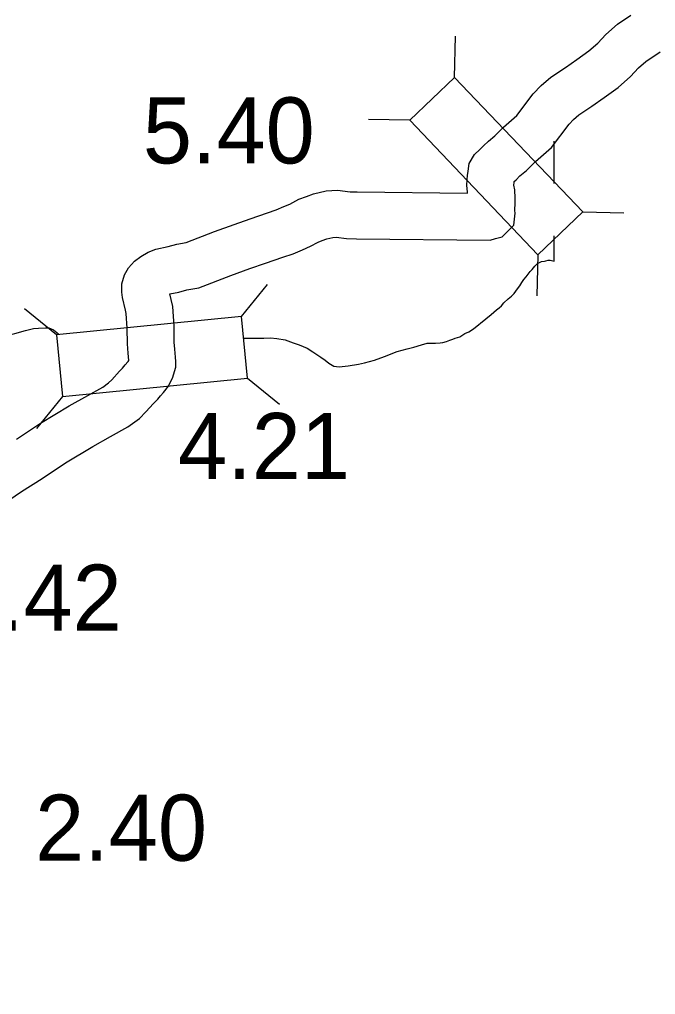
# Model space of a CAD drawing. Extents: x 0 to 3171, y 0 to 2059.
# Drawn here: x 276 to 357.4, y 1415.2 to 1539.9 of the extents above; entities that cross this region are included whole.
import ezdxf

# ---------------------------------------------------------------- set-up
doc = ezdxf.new("R2010")
doc.units = 0
for name, color, linetype in [('Default', 7, 'Continuous'), ('Level 10', 7, 'Continuous'), ('Level 20', 7, 'Continuous'), ('Level 58', 7, 'Continuous'), ('Level 8', 7, 'Continuous')]:
    doc.layers.add(name, color=color, linetype=linetype)

msp = doc.modelspace()

# ---------------------------------------------------------------- linework, layer by layer
at = {"layer": 'Default'}
msp.add_circle((410.95, 1647.45), 386.47, dxfattribs=at)
msp.add_circle((410.95, 1647.45), 386.47, dxfattribs=at)
at = {"layer": 'Level 10'}
for points in [[(275.61, 1486.19), (278.67, 1488.24), (282.36, 1490.48), (284.75, 1491.8), (286.64, 1492.85), (287.4, 1493.4), (287.79, 1493.82), (288.79, 1494.89), (289.18, 1495.3), (289.51, 1495.71), (289.87, 1496.09), (289.92, 1496.15), (289.98, 1496.28), (289.89, 1497.21), (289.8, 1498.39), (289.79, 1500.42), (289.66, 1502.27), (289.55, 1502.72), (289.18, 1504.35), (289.1, 1505.03), (289.1, 1506.1), (289.42, 1507.24), (289.96, 1508.14), (290.72, 1508.97), (291.54, 1509.58), (292.46, 1510.13), (293.45, 1510.53), (295.01, 1510.87), (296.14, 1511.16), (297.31, 1511.37), (300.95, 1512.77), (303.47, 1513.68), (305.51, 1514.38), (307.73, 1515.15), (308.85, 1515.54), (309.81, 1515.95), (310.58, 1516.29), (311.72, 1516.91), (312.71, 1517.27), (313.62, 1517.59), (315.21, 1517.96), (316.7, 1518.05), (318.28, 1517.85), (319.18, 1517.83), (333.33, 1517.69), (333.3, 1517.85), (333.22, 1518.65), (333.28, 1519.44), (333.31, 1519.95), (333.39, 1520.5), (333.54, 1521.49), (334.22, 1522.61), (334.88, 1523.28), (335.36, 1523.73), (335.99, 1524.33), (336.8, 1525.02), (337.92, 1526.12), (339.63, 1527.63), (341.71, 1530.4), (342.72, 1531.46), (343.96, 1532.52), (345.84, 1533.75), (347.31, 1534.79), (348.85, 1535.89), (349.97, 1536.88), (350.99, 1537.99), (352.48, 1539.3), (354.21, 1540.45)], [(275.61, 1486.19), (278.67, 1488.24), (282.36, 1490.48), (284.75, 1491.8), (286.64, 1492.85), (287.4, 1493.4), (287.79, 1493.82), (288.79, 1494.89), (289.18, 1495.3), (289.51, 1495.71), (289.87, 1496.09), (289.92, 1496.15), (289.98, 1496.28), (289.89, 1497.21), (289.8, 1498.39), (289.79, 1500.42), (289.66, 1502.27), (289.55, 1502.72), (289.18, 1504.35), (289.1, 1505.03), (289.1, 1506.1), (289.42, 1507.24), (289.96, 1508.14), (290.72, 1508.97), (291.54, 1509.58), (292.46, 1510.13), (293.45, 1510.53), (295.01, 1510.87), (296.14, 1511.16), (297.31, 1511.37), (300.95, 1512.77), (303.47, 1513.68), (305.51, 1514.38), (307.73, 1515.15), (308.85, 1515.54), (309.81, 1515.95), (310.58, 1516.29), (311.72, 1516.91), (312.71, 1517.27), (313.62, 1517.59), (315.21, 1517.96), (316.7, 1518.05), (318.28, 1517.85), (319.18, 1517.83), (333.33, 1517.69), (333.3, 1517.85), (333.22, 1518.65), (333.28, 1519.44), (333.31, 1519.95), (333.39, 1520.5), (333.54, 1521.49), (334.22, 1522.61), (334.88, 1523.28), (335.36, 1523.73), (335.99, 1524.33), (336.8, 1525.02), (337.92, 1526.12), (339.63, 1527.63), (341.71, 1530.4), (342.72, 1531.46), (343.96, 1532.52), (345.84, 1533.75), (347.31, 1534.79), (348.85, 1535.89), (349.97, 1536.88), (350.99, 1537.99), (352.48, 1539.3), (354.21, 1540.45)], [(273.08, 1477.38), (276.26, 1479.51), (278.88, 1481.16), (281.9, 1483.18), (285.37, 1485.29), (287.66, 1486.56), (289.85, 1487.78), (291.37, 1488.86), (292.18, 1489.72), (293.15, 1490.77), (293.68, 1491.32), (294.02, 1491.75), (294.43, 1492.17), (295.06, 1492.99), (295.62, 1494.16), (295.72, 1494.46), (295.99, 1495.43), (295.99, 1496.15), (295.97, 1496.71), (295.87, 1497.73), (295.8, 1498.63), (295.78, 1500.65), (295.61, 1503.16), (295.4, 1504.07), (295.23, 1504.78), (296.39, 1505.03), (297.41, 1505.3), (298.92, 1505.56), (303.04, 1507.14), (305.47, 1508.02), (307.47, 1508.71), (309.69, 1509.48), (311, 1509.93), (312.2, 1510.44), (313.23, 1510.9), (314.21, 1511.43), (314.73, 1511.62), (315.3, 1511.82), (316.08, 1512), (316.5, 1512.03), (317.84, 1511.86), (319.09, 1511.83), (336.22, 1511.66), (336.89, 1511.87), (337.75, 1512.11), (339.23, 1513.58), (339.4, 1515.12), (339.37, 1515.48), (339.37, 1515.65), (339.39, 1516.29), (339.39, 1517.03), (339.36, 1518.11), (339.25, 1518.72), (339.27, 1519.06), (339.28, 1519.17), (339.52, 1519.4), (340.01, 1519.88), (340.85, 1520.59), (342, 1521.72), (344.06, 1523.53), (346.3, 1526.51), (346.85, 1527.09), (347.57, 1527.71), (349.22, 1528.79), (350.79, 1529.9), (352.6, 1531.19), (354.17, 1532.59), (355.19, 1533.69), (356.14, 1534.53), (357.97, 1535.74)], [(273.08, 1477.38), (276.26, 1479.51), (278.88, 1481.16), (281.9, 1483.18), (285.37, 1485.29), (287.66, 1486.56), (289.85, 1487.78), (291.37, 1488.86), (292.18, 1489.72), (293.15, 1490.77), (293.68, 1491.32), (294.02, 1491.75), (294.43, 1492.17), (295.06, 1492.99), (295.62, 1494.16), (295.72, 1494.46), (295.99, 1495.43), (295.99, 1496.15), (295.97, 1496.71), (295.87, 1497.73), (295.8, 1498.63), (295.78, 1500.65), (295.61, 1503.16), (295.4, 1504.07), (295.23, 1504.78), (296.39, 1505.03), (297.41, 1505.3), (298.92, 1505.56), (303.04, 1507.14), (305.47, 1508.02), (307.47, 1508.71), (309.69, 1509.48), (311, 1509.93), (312.2, 1510.44), (313.23, 1510.9), (314.21, 1511.43), (314.73, 1511.62), (315.3, 1511.82), (316.08, 1512), (316.5, 1512.03), (317.84, 1511.86), (319.09, 1511.83), (336.22, 1511.66), (336.89, 1511.87), (337.75, 1512.11), (339.23, 1513.58), (339.4, 1515.12), (339.37, 1515.48), (339.37, 1515.65), (339.39, 1516.29), (339.39, 1517.03), (339.36, 1518.11), (339.25, 1518.72), (339.27, 1519.06), (339.28, 1519.17), (339.52, 1519.4), (340.01, 1519.88), (340.85, 1520.59), (342, 1521.72), (344.06, 1523.53), (346.3, 1526.51), (346.85, 1527.09), (347.57, 1527.71), (349.22, 1528.79), (350.79, 1529.9), (352.6, 1531.19), (354.17, 1532.59), (355.19, 1533.69), (356.14, 1534.53), (357.97, 1535.74)]]:
    msp.add_lwpolyline(points, dxfattribs=at)
at = {"layer": 'Level 20'}
for p, q in [((331.65, 1532.46), (331.78, 1537.74)), ((331.65, 1532.46), (331.78, 1537.74)), ((325.92, 1527), (320.64, 1527.12)), ((325.92, 1527), (320.64, 1527.12)), ((348.05, 1515.27), (353.33, 1515.15)), ((348.05, 1515.27), (353.33, 1515.15)), ((342.32, 1509.8), (342.2, 1504.53)), ((342.32, 1509.8), (342.2, 1504.53)), ((304.38, 1501.89), (307.72, 1505.98)), ((304.38, 1501.89), (307.72, 1505.98)), ((280.73, 1499.55), (276.65, 1502.9)), ((280.73, 1499.55), (276.65, 1502.9)), ((305.16, 1494.01), (309.24, 1490.67)), ((305.16, 1494.01), (309.24, 1490.67)), ((281.51, 1491.67), (278.16, 1487.59)), ((281.51, 1491.67), (278.16, 1487.59))]:
    msp.add_line(p, q, dxfattribs=at)
for points in [[(348.05, 1515.27), (331.65, 1532.46), (325.92, 1527), (342.32, 1509.8)], [(348.05, 1515.27), (331.65, 1532.46), (325.92, 1527), (342.32, 1509.8)], [(281.51, 1491.67), (305.16, 1494.01), (304.38, 1501.89), (280.73, 1499.55)], [(281.51, 1491.67), (305.16, 1494.01), (304.38, 1501.89), (280.73, 1499.55)]]:
    msp.add_lwpolyline(points, close=True, dxfattribs=at)
at = {"layer": 'Level 8'}
for points in [[(344.41, 1518.91), (344.4, 1524.32)], [(344.41, 1518.91), (344.4, 1524.32)], [(332.97, 1499.72), (333.47, 1499.95), (334.09, 1500.31), (335.67, 1501.59), (336.35, 1502.15), (337.03, 1502.75), (337.37, 1503.03), (337.67, 1503.25), (337.97, 1503.63), (338.53, 1504.18), (338.93, 1504.52), (339.27, 1504.86), (339.71, 1505.42), (339.99, 1505.84), (340.27, 1506.24), (340.53, 1506.62), (340.81, 1506.98), (341.05, 1507.32), (341.33, 1507.66), (341.6, 1507.92), (341.76, 1508.12), (341.94, 1508.32), (342.26, 1508.66), (342.44, 1508.78), (342.76, 1508.92), (343.16, 1509), (343.33, 1509.04), (343.63, 1509.1), (343.87, 1509.09), (344.41, 1508.97), (344.41, 1512.24)], [(332.97, 1499.72), (333.47, 1499.95), (334.09, 1500.31), (335.67, 1501.59), (336.35, 1502.15), (337.03, 1502.75), (337.37, 1503.03), (337.67, 1503.25), (337.97, 1503.63), (338.53, 1504.18), (338.93, 1504.52), (339.27, 1504.86), (339.71, 1505.42), (339.99, 1505.84), (340.27, 1506.24), (340.53, 1506.62), (340.81, 1506.98), (341.05, 1507.32), (341.33, 1507.66), (341.6, 1507.92), (341.76, 1508.12), (341.94, 1508.32), (342.26, 1508.66), (342.44, 1508.78), (342.76, 1508.92), (343.16, 1509), (343.33, 1509.04), (343.63, 1509.1), (343.87, 1509.09), (344.41, 1508.97), (344.41, 1512.24)], [(274.87, 1499.59), (275.39, 1499.72), (276.77, 1500.12), (277.79, 1500.38), (278.43, 1500.43), (279.33, 1500.45), (279.77, 1500.45), (280.33, 1500.21), (281, 1499.7)], [(274.87, 1499.59), (275.39, 1499.72), (276.77, 1500.12), (277.79, 1500.38), (278.43, 1500.43), (279.33, 1500.45), (279.77, 1500.45), (280.33, 1500.21), (281, 1499.7)], [(304.71, 1499.15), (306.34, 1499.13), (307.27, 1499.15), (308.11, 1499.19), (308.93, 1499.1), (309.99, 1498.92), (310.99, 1498.54), (311.78, 1498.28), (312.82, 1497.87), (313.54, 1497.37), (314.18, 1496.95), (314.53, 1496.69), (315.09, 1496.32), (315.55, 1495.94), (316.19, 1495.56), (316.89, 1495.48), (318.04, 1495.59), (319.36, 1495.79), (320.12, 1495.97), (321.42, 1496.33), (322.7, 1496.8), (324.32, 1497.44), (325.6, 1497.77), (326.44, 1497.99), (327.43, 1498.27), (328.13, 1498.49), (329.21, 1498.51), (329.81, 1498.54), (330.15, 1498.58), (330.61, 1498.72), (331.03, 1498.88), (331.43, 1499.02), (331.73, 1499.12), (332.35, 1499.32), (332.97, 1499.72)], [(304.71, 1499.15), (306.34, 1499.13), (307.27, 1499.15), (308.11, 1499.19), (308.93, 1499.1), (309.99, 1498.92), (310.99, 1498.54), (311.78, 1498.28), (312.82, 1497.87), (313.54, 1497.37), (314.18, 1496.95), (314.53, 1496.69), (315.09, 1496.32), (315.55, 1495.94), (316.19, 1495.56), (316.89, 1495.48), (318.04, 1495.59), (319.36, 1495.79), (320.12, 1495.97), (321.42, 1496.33), (322.7, 1496.8), (324.32, 1497.44), (325.6, 1497.77), (326.44, 1497.99), (327.43, 1498.27), (328.13, 1498.49), (329.21, 1498.51), (329.81, 1498.54), (330.15, 1498.58), (330.61, 1498.72), (331.03, 1498.88), (331.43, 1499.02), (331.73, 1499.12), (332.35, 1499.32), (332.97, 1499.72)]]:
    msp.add_lwpolyline(points, dxfattribs=at)

# ---------------------------------------------------------------- texts
at = {"layer": 'Level 58'}
for s, p in [('5.40', (291.78, 1521.48)), ('5.40', (291.78, 1521.48)), ('4.21', (296.29, 1481.11)), ('4.21', (296.29, 1481.11)), ('3.42', (267.1, 1461.72)), ('3.42', (267.1, 1461.72)), ('2.40', (278, 1432.29)), ('2.40', (278, 1432.29))]:
    msp.add_text(s, height=8.448, dxfattribs=at).set_placement(p)

doc.saveas('drawing.dxf')
